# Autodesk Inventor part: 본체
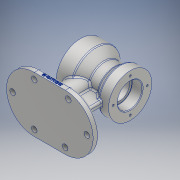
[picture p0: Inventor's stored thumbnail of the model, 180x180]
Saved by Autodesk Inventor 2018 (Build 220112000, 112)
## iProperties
Created: 2020-01
Part Number: 본체
Material: 알루미늄 6061
Document SubType Name: Modeling
Designer: Administrator
Density: 2.7 g/cm^3
Appearance: 알루미늄 - 평지
Mass: 963.622 g
Surface Area: 670.265 cm^2
Volume: 356.897 cm^3
Author: Administrator
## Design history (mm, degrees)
sketch "스케치1"
  geometry: L1 (0, 0)-(24, 0); L2 (24, 0)-(24, 40); L3 (24, 40)-(0, 40); L4 (0, 40)-(0, 0); L5 (24, 0)-(33.358, 0); L6 (24, 28.653)-(24, 0); L7 (33.358, 0)-(55.062, 0); L8 (55.062, 0)-(55.062, 27.5); L9 (55.062, 0)-(64, 0); L10 (64, 0)-(64, 27.491); L11 (55.062, 27.5)-(55.062, 0); L12 (64, 0)-(80, 0); L13 (80, 0)-(80, 35); L14 (80, 35)-(64, 35); L15 (64, 35)-(64, 0); L16 (24, 40)-(38.897, 27.5); L17 (64, 35)-(55.062, 27.5); L18 (55.062, 27.5)-(38.897, 27.5); L19 (38.897, 27.5)-(38.897, 0)
  constraints: 38 end point, 5 horizontal, 5 parallel, 5 perpendicular, 1 point on line
  dimensions: "d0" = 80 distance between parallel lines of L13 L4; "d1" = 24 distance between parallel lines of L6 L4; "d2" = 16 distance between parallel lines of L13 L10; "d6" = 40 deg angle of L18 L16; "d7" = 40 deg angle of L17 L18; "d8" = 80 diameter of L3 L1; "d9" = 70 diameter of L14 L12; "d41" = 55 diameter of L18 L7
revolve "회전1" sketch "스케치1" stored, may be unused: angle "d10" = 90 deg
sketch "스케치2"
  geometry: L1 (40, 0)-(40, -80); L2 (0, -40)-(0, 40) reference; L3 (-30, -80)-(110, -80); L4 (110, -80)-(110, -90); L5 (110, -90)-(-30, -90); L6 (-30, -90)-(-30, -80); 1 further point
  constraints: 10 end point, 2 parallel, 1 horizontal, 1 perpendicular, 1 vertical
  dimensions: "d11" = 80 distance of L1.start L1.end; "d12" = 40 distance between parallel lines of L1 L2; "d13" = 140 distance between parallel lines of L4 L6; "d14" = 70 distance between parallel lines of L1 L6; "d68" = 10 distance between parallel lines of L5 L3
extrude "돌출1" join sketch "스케치2" stored distance "d15" = 90; taper "d16" = 0 deg
fillet "모깎기1" dims "d17" = 45
sketch "스케치3"
  geometry: L1 (0, 0)-(50, 0) reference; L2 (50, -90)-(0, -90) reference; L3 (28.199, -40)-(55, -40); L4 (28.199, -50)-(55, -50); L5 (55, -40)-(55, -50); L6 (55, -79.641)-(55, -80); C1 r 4.5 at (0, -10); C2 r 4.5 at (50, -10); C3 r 4.5 at (85, -45); C4 r 4.5 at (55, -79.641); C5 r 4.5 at (0, -80); C6 r 4.5 at (-35, -45); A1 r 45 centre (50, -45) between (50, -90) and (50, 0) reference; A2 r 45 centre (0, -45) between (0, 0) and (0, -90) reference; A3 r 16 centre (13, -45) between (28.199, -40) and (28.199, -50); 1 further point
  constraints: 8 end point, 7 centre point, 2 point on circle, 1 coincident
  dimensions: "d20" = 32 diameter of A3; "d24" = 9 diameter of C1; "d25" = 9 diameter of C2; "d26" = 9 diameter of C3; "d27" = 9 diameter of C4; "d28" = 9 diameter of C5; "d29" = 9 diameter of C6
extrude "돌출2" cut sketch "스케치3" distance "d30" = 90; taper "d31" = 0 deg
extrude "돌출3" join sketch "스케치3" stored distance "d32" = 90; taper "d33" = 0 deg; dims "d0" = 80, "d1" = 24, "d2" = 16, "d6" = 40 deg, "d7" = 40 deg, "d8" = 80, "d9" = 70, "d41" = 55
sketch "스케치4"
  geometry: L1 (0, 0)-(20, 0); L2 (20, 0)-(20, 25.7); L3 (19.7, 26)-(0, 26); L4 (0, 26)-(0, 0); L5 (20, 0)-(63, 0); L6 (63, 0)-(63, 16); L7 (63, 16)-(20, 16); L8 (20, 16)-(20, 0); L9 (80, -35)-(80, 35) reference; L10 (63, 0)-(80, 0); L11 (80, 0)-(80, 20); L12 (80, 20)-(63.3, 20); L13 (63, 19.7)-(63, 0); A1 r 0.3 centre (63.3, 19.7) between (63.3, 20) and (63, 19.7); A2 r 0.3 centre (19.7, 25.7) between (20, 25.7) and (19.7, 26)
  constraints: 24 end point, 6 parallel, 4 point on circle, 4 tangent, 3 horizontal, 3 perpendicular, 2 centre point, 1 equal radius, 1 point on line
  dimensions: "d34" = 17 distance between parallel lines of L9 L6; "d35" = 20 distance between parallel lines of L2 L4; "d36" = 52 diameter of L3 L1; "d37" = 32 diameter of L7 L5; "d38" = 40 diameter of L12 L10; "d39" = 0.3 radius of A1
revolve "회전2" sketch "스케치4" stored, may be unused: angle "d40" = 90 deg
sketch "스케치5"
  geometry: A1 r 33 centre (0, 0) between (0, 33) and (33, 0); 3 further points
  constraints: 4 point on circle, 1 centre point, 1 coincident
  dimensions: "d42" = 66 diameter of A1
hole "구멍1" sketch "스케치5" at (0, 33), (33, 0), (-33, 0), (0, -33) diameter "d43" = 3.242; stored, may be unused: countersink angle "d47" = 90 deg, drill point angle "d49" = 118 deg; dims "d44" = 9, "d45" = 4, "d46" = 2, "d48" = 11
sketch "스케치6"
  geometry: A1 r 27.5 centre (0, 0) between (0, 27.5) and (27.5, 0); 3 further points
  constraints: 4 point on circle, 1 centre point, 1 coincident
  dimensions: "d50" = 55 diameter of A1
hole "구멍2" sketch "스케치6" at (0, 27.5), (27.5, 0), (-27.5, 0), (0, -27.5) diameter "d51" = 3.242; stored, may be unused: countersink angle "d55" = 90 deg, drill point angle "d57" = 118 deg; dims "d52" = 9, "d53" = 4, "d54" = 2, "d56" = 11
sketch "스케치7"
  geometry: L1 (-30, -80)-(15, -80) reference; L2 (110, -90)-(65, -90) reference; 2 further points
  constraints: 1 other
  dimensions: "d58" = 70 horizontal distance of point (40, -86) L1.start; "d59" = 4 distance from line of point (40, -86) L2
feature "엠보싱1" sketch "스케치7" dims "d60" = 0.5, "d61" = 0
chamfer "모따기1" distance "d62" = 1; stored, may be unused: second distance "d63" = 2, angle "d64" = 45 deg
fillet "모깎기2" dims "d65" = 3
fillet "모깎기3" dims "d66" = 3
fillet "모깎기4" dims "d67" = 3
fillet "모깎기5" dims "d69" = 3
node "솔리드1"
